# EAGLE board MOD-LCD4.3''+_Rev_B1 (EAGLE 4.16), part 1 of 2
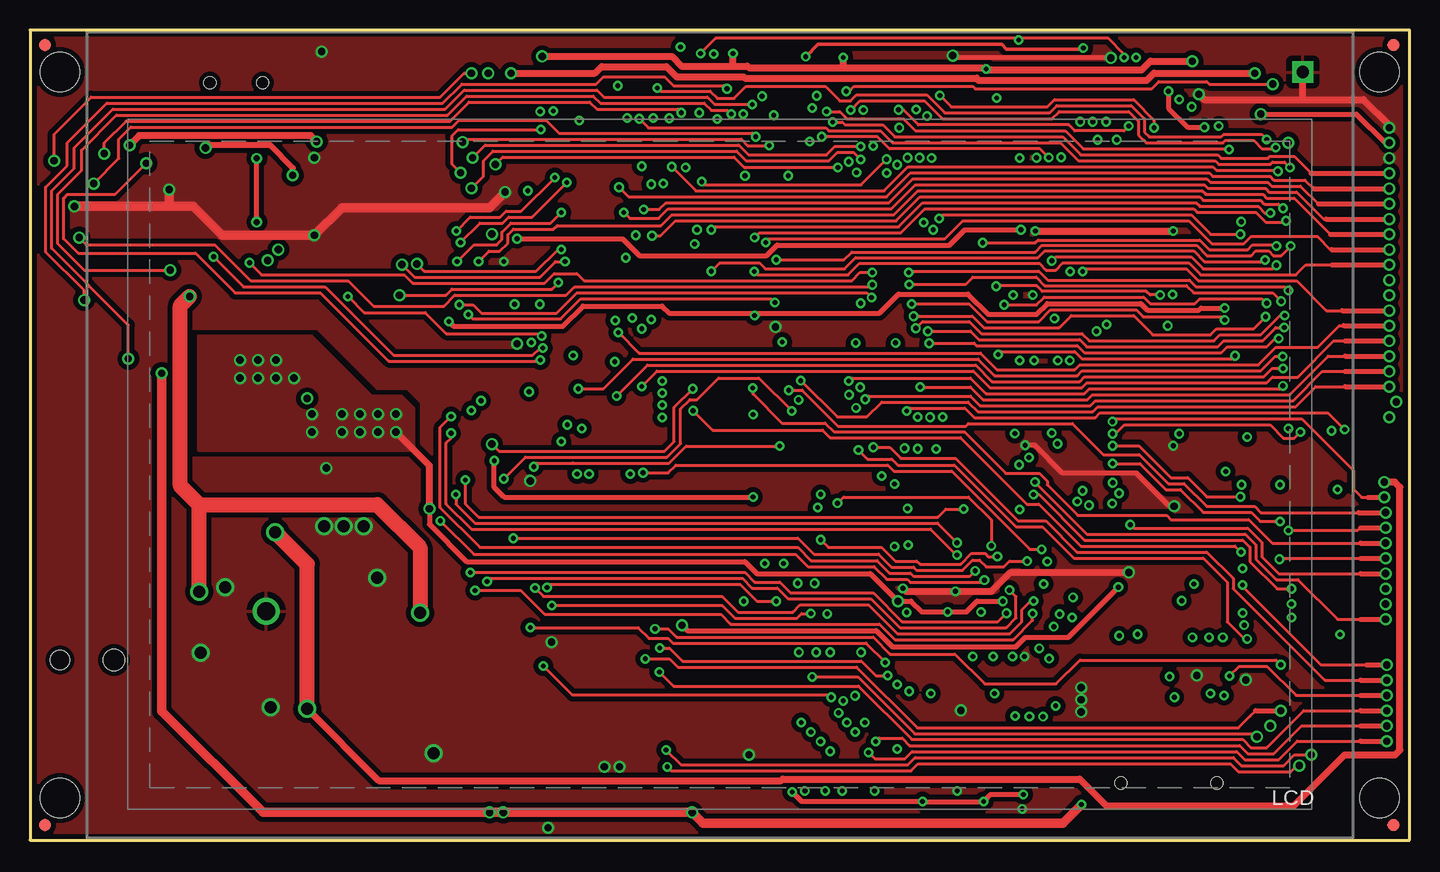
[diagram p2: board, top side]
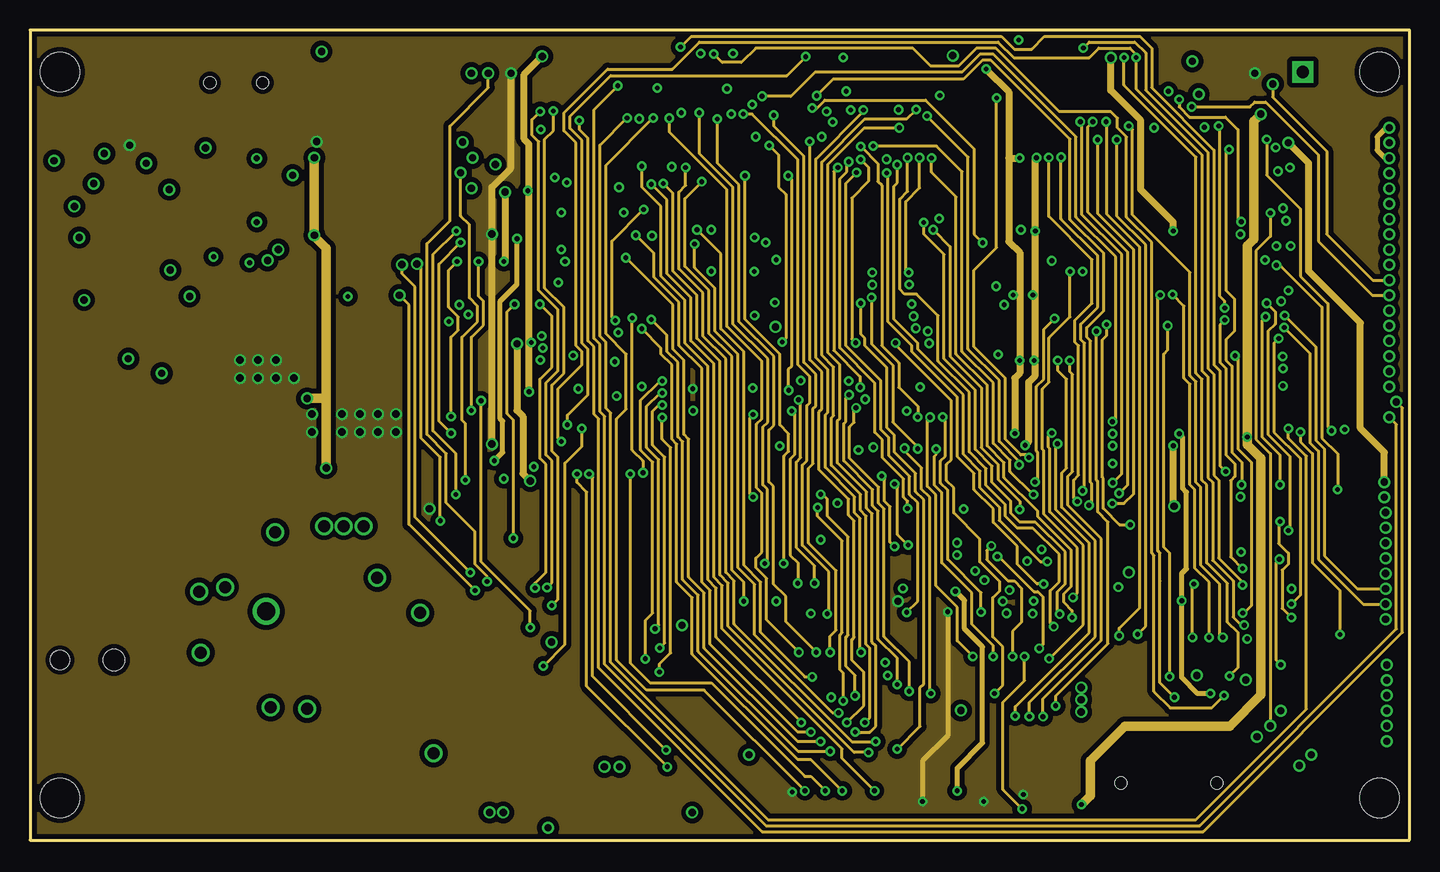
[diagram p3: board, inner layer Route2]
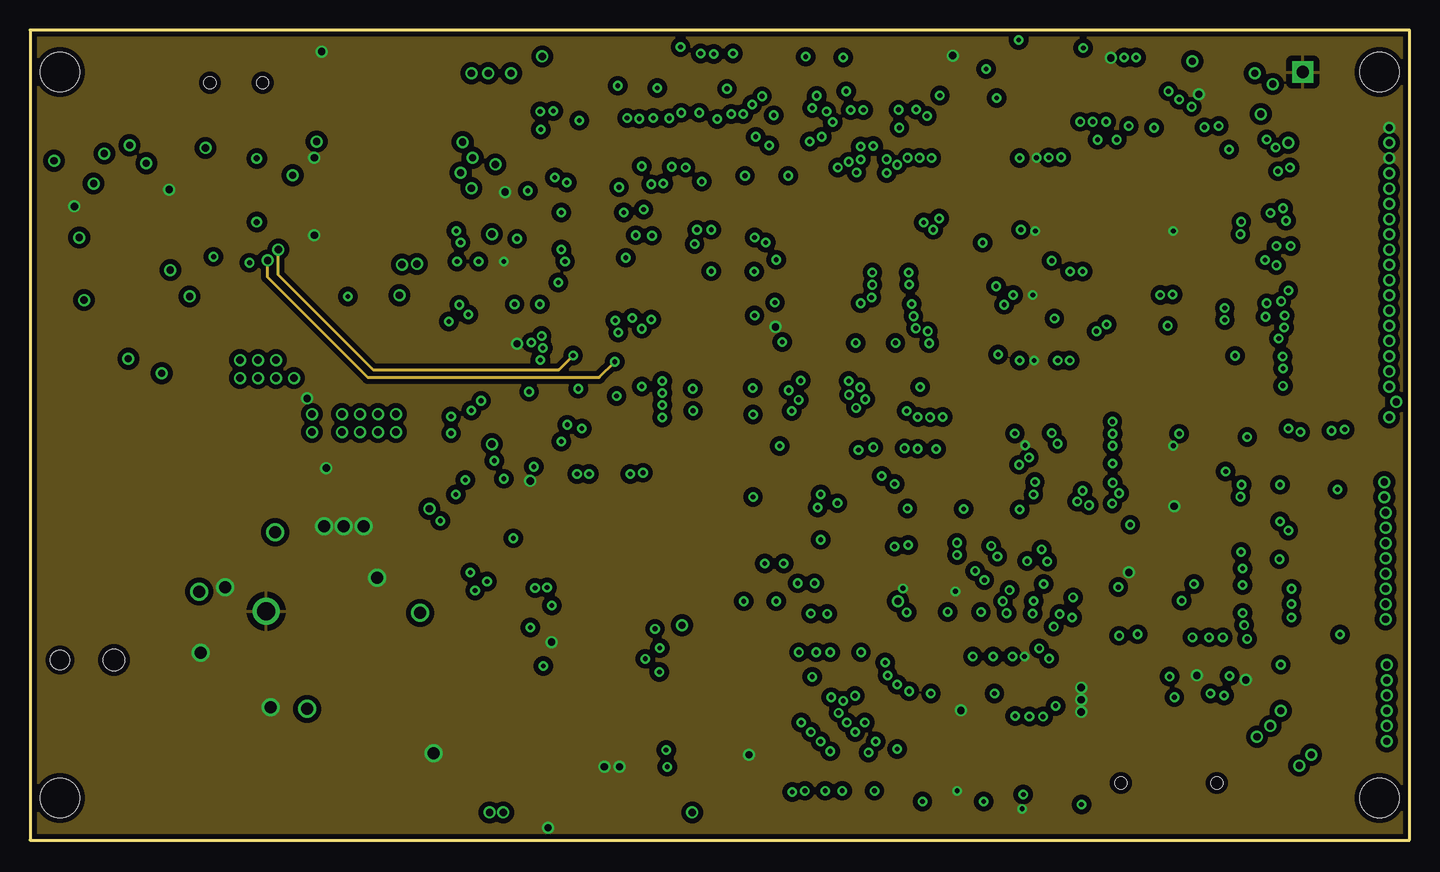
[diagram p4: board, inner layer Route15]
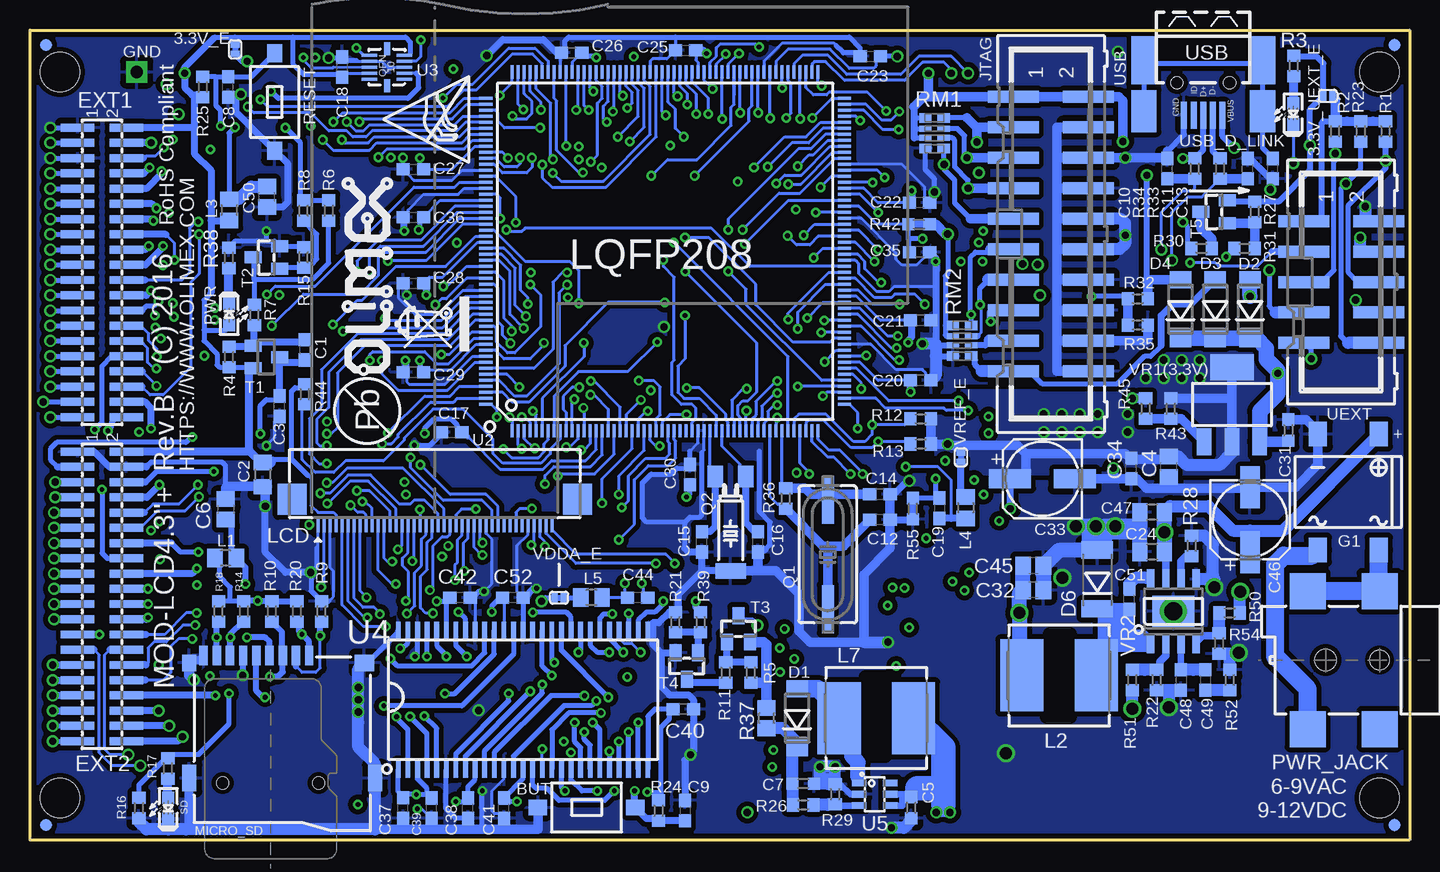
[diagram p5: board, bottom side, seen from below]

Size 115 x 67.5 mm. Coordinates in mm from the lower left corner, seen from the top.
Outline: 0,0 115,0 115,67.5 0,67.5 0,0
Copper layers (1*2*15*16): Top 0.035mm / dielectric 0.5mm / Route2 0.035mm / dielectric 0.5mm / Route15 0.035mm / dielectric 0.5mm / Bottom 0.035mm
Design rules "default": minimum track width 0.2mm, minimum drill 0.4mm, track to track 0.2mm, track to pad 0.2mm, pad to pad 0.2mm, via to via 0.2mm, smd to smd 0mil, copper to edge 0.25mm, drill to drill 0.2mm, minimum pad ring 0.25mm, minimum via ring 0.2mm, stop-mask expansion 2mil, vias tented up to drill 25mil, thermal gap 20mil
Net classes: 1 pwr: width 0.25 mm; 2 gnd: width 0.25 mm, clearance 0.4 mm
Holes 3.3 mm at 2.5,64 2.5,3.5 112.5,3.5 112.5,64
bRestrict: 9 lines

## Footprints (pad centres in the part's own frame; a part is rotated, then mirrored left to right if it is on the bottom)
SJ_1_SMALLER_CLOSE = smd 0.508 x 0.762: 1 -0.381,0; 2 0.381,0
SJ_1_SMALLER = smd 0.508 x 0.762: 1 -0.381,0; 2 0.381,0
SW-TAKT_6X3.5_SMD = smd 1.27 x 1.524: P$1 0,4.064; P$2 0,-4.064
C0603 = smd 1.1 x 1: 1 -0.85,0; 2 0.85,0
C0805_5MIL_DWS = smd 1.27 x 1.524: 1 -1.016,0; 2 1.016,0
C0805 = smd 1.3 x 1.5: 1 -0.85,0; 2 0.85,0
C0603_DWS = smd 1.016 x 1.016: 1 -0.889,0; 2 0.889,0
153CLV-0605 = smd 3.5 x 1.6: + -2.7,0; - 2.7,0
MLL-41 = smd 1.45 x 1.8: A 2.445,0; K -2.445,0
MELF-MLL41 = smd 1.45 x 2.6: 1 -2.445,0; 2 2.445,0
ML40_50MILS_M = smd 0.66 x 2.794: 1 -12.065,-2.032; 2 -12.065,2.032; 3 -10.795,-2.032; 4 -10.795,2.032; 5 -9.525,-2.032; 6 -9.525,2.032; 7 -8.255,-2.032; 8 -8.255,2.032; 9 -6.985,-2.032; 10 -6.985,2.032; 11 -5.715,-2.032; 12 -5.715,2.032; 13 -4.445,-2.032; 14 -4.445,2.032; 15 -3.175,-2.032; 16 -3.175,2.032; 17 -1.905,-2.032; 18 -1.905,2.032; 19 -0.635,-2.032; 20 -0.635,2.032; 21 0.635,-2.032; 22 0.635,2.032; 23 1.905,-2.032; 24 1.905,2.032; 25 3.175,-2.032; 26 3.175,2.032; 27 4.445,-2.032; 28 4.445,2.032; 29 5.715,-2.032; 30 5.715,2.032; 31 6.985,-2.032; 32 6.985,2.032; 33 8.255,-2.032; 34 8.255,2.032; 35 9.525,-2.032; 36 9.525,2.032; 37 10.795,-2.032; 38 10.795,2.032; 39 12.065,-2.032; 40 12.065,2.032
DB104_SMD = smd 1.524 x 2.032: + -2.54,-4.826; - 2.54,-4.826; AC1 2.54,4.826; AC2 -2.54,4.826
TEST_PAD40/70/SQUARE = drill 1.016 pad 1.778 square: P$1 0,0
ML20_S = smd 1 x 4.25: 1 -11.43,-3.125; 2 -11.43,3.125; 3 -8.89,-3.125; 4 -8.89,3.125; 5 -6.35,-3.125; 6 -6.35,3.125; 7 -3.81,-3.125; 8 -3.81,3.125; 9 -1.27,-3.125; 10 -1.27,3.125; 11 1.27,-3.125; 12 1.27,3.125; 13 3.81,-3.125; 14 3.81,3.125; 15 6.35,-3.125; 16 6.35,3.125; 17 8.89,-3.125; 18 8.89,3.125; 19 11.43,-3.125; 20 11.43,3.125
L0805 = smd 1.27 x 1.524: 1 -0.889,0; 2 0.889,0
8X8MM_3131 = smd 3.6 x 6: 1 -3.1,0; 2 3.1,0
GFT043(40PINS) = smd 0.25 x 1.3 bottom: 1 -33.5,7.45; 2 -33,7.45; 3 -32.5,7.45; 4 -32,7.45; 5 -31.5,7.45; 6 -31,7.45; 7 -30.5,7.45; 8 -30,7.45; 9 -29.5,7.45; 10 -29,7.45; 11 -28.5,7.45; 12 -28,7.45; 13 -27.5,7.45; 14 -27,7.45; 15 -26.5,7.45; 16 -26,7.45; 17 -25.5,7.45; 18 -25,7.45; 19 -24.5,7.45; 20 -24,7.45; 21 -23.5,7.45; 22 -23,7.45; 23 -22.5,7.45; 24 -22,7.45; 25 -21.5,7.45; 26 -21,7.45; 27 -20.5,7.45; 28 -20,7.45; 29 -19.5,7.45; 30 -19,7.45; 31 -18.5,7.45; 32 -18,7.45; 33 -17.5,7.45; 34 -17,7.45; 35 -16.5,7.45; 36 -16,7.45; 37 -15.5,7.45; 38 -15,7.45; 39 -14.5,7.45; 40 -14,7.45 | smd 2.4 x 2.6 bottom: P1 -11.85,5.35; P2 -35.65,5.35
TFC-WPAPR-08 = smd 1.6 x 0.7: 1 -7.375,2.25; 2 -7.375,1.15; 3 -7.375,0.05; 4 -7.375,-1.05; 5 -7.375,-2.15; 6 -7.375,-3.25; 7 -7.375,-4.35; 8 -7.375,-5.45; 9 -7.375,-6.55 | smd 1.4 x 1.2: 10 -6.75,-7.75 | smd 1.4 x 1.6: 11 -6.75,6.85 | smd 2.2 x 1.2: 12 2.85,-7.75; 13 2.85,7.75 | hole 1: 3.25,-4.95; 3.25,3.05
LED-0603 = smd 1.016 x 1.016: A 0.889,0; C -0.889,0
PWR-JACK-SMD = smd 3 x 3: 1 6,5.75; 2 0,-5.75; 3 6,-5.75; 4 0,5.75 | hole 1.6: 0,0 | hole 1.8: 4.5,0
HC49/SMD2_THIN&SHORT = smd 4 x 1: 1 -4.564,0; 2 4.564,0
TC26H_3_REPAIR_SMD = smd 1.27 x 1.778: 1 -1.27,0; 2 1.27,0 | smd 2.54 x 1.27: GND 0,7.874
R0603 = smd 1 x 1.1: 1 -0.85,0; 2 0.85,0
R0805 = smd 1.3 x 1.5: 1 -0.85,0; 2 0.85,0
0603_0R = smd 1.016 x 1.016: 1 -0.889,0; 2 0.889,0
R_MATRIX_4 = smd 0.762 x 1.016: 1.1 -1.27,-0.762; 1.2 -1.27,0.762; 4.1 1.27,-0.762; 4.2 1.27,0.762 | smd 0.508 x 1.016: 2.1 -0.381,-0.762; 2.2 -0.381,0.762; 3.1 0.381,-0.762; 3.2 0.381,0.762
SOT23 = smd 1.4 x 1: 1 1.1,-0.95; 2 1.1,0.95; 3 -1.1,0
LQFP208 = smd 0.254 x 1.1: 1 -12.75,-14.95; 2 -12.25,-14.95; 3 -11.75,-14.95; 4 -11.25,-14.95; 5 -10.75,-14.95; 6 -10.25,-14.95; 7 -9.75,-14.95; 8 -9.25,-14.95; 9 -8.75,-14.95; 10 -8.25,-14.95; 11 -7.75,-14.95; 12 -7.25,-14.95; 13 -6.75,-14.95; 14 -6.25,-14.95; 15 -5.75,-14.95; 16 -5.25,-14.95; 17 -4.75,-14.95; 18 -4.25,-14.95; 19 -3.75,-14.95; 20 -3.25,-14.95; 21 -2.75,-14.95; 22 -2.25,-14.95; 23 -1.75,-14.95; 24 -1.25,-14.95; 25 -0.75,-14.95; 26 -0.25,-14.95; 27 0.25,-14.95; 28 0.75,-14.95; 29 1.25,-14.95; 30 1.75,-14.95; 31 2.25,-14.95; 32 2.75,-14.95; 33 3.25,-14.95; 34 3.75,-14.95; 35 4.25,-14.95; 36 4.75,-14.95; 37 5.25,-14.95; 38 5.75,-14.95; 39 6.25,-14.95; 40 6.75,-14.95; 41 7.25,-14.95; 42 7.75,-14.95; 43 8.25,-14.95; 44 8.75,-14.95; 45 9.25,-14.95; 46 9.75,-14.95; 47 10.25,-14.95; 48 10.75,-14.95; 49 11.25,-14.95; 50 11.75,-14.95; 51 12.25,-14.95; 52 12.75,-14.95; 105 12.75,14.95; 106 12.25,14.95; 107 11.75,14.95; 108 11.25,14.95; 109 10.75,14.95; 110 10.25,14.95; 111 9.75,14.95; 112 9.25,14.95; 113 8.75,14.95; 114 8.25,14.95; 115 7.75,14.95; 116 7.25,14.95; 117 6.75,14.95; 118 6.25,14.95; 119 5.75,14.95; 120 5.25,14.95; 121 4.75,14.95; 122 4.25,14.95; 123 3.75,14.95; 124 3.25,14.95; 125 2.75,14.95; 126 2.25,14.95; 127 1.75,14.95; 128 1.25,14.95; 129 0.75,14.95; 130 0.25,14.95; 131 -0.25,14.95; 132 -0.75,14.95; 133 -1.25,14.95; 134 -1.75,14.95; 135 -2.25,14.95; 136 -2.75,14.95; 137 -3.25,14.95; 138 -3.75,14.95; 139 -4.25,14.95; 140 -4.75,14.95; 141 -5.25,14.95; 142 -5.75,14.95; 143 -6.25,14.95; 144 -6.75,14.95; 145 -7.25,14.95; 146 -7.75,14.95; 147 -8.25,14.95; 148 -8.75,14.95; 149 -9.25,14.95; 150 -9.75,14.95; 151 -10.25,14.95; 152 -10.75,14.95; 153 -11.25,14.95; 154 -11.75,14.95; 155 -12.25,14.95; 156 -12.75,14.95 | smd 1.1 x 0.254: 53 14.95,-12.75; 54 14.95,-12.25; 55 14.95,-11.75; 56 14.95,-11.25; 57 14.95,-10.75; 58 14.95,-10.25; 59 14.95,-9.75; 60 14.95,-9.25; 61 14.95,-8.75; 62 14.95,-8.25; 63 14.95,-7.75; 64 14.95,-7.25; 65 14.95,-6.75; 66 14.95,-6.25; 67 14.95,-5.75; 68 14.95,-5.25; 69 14.95,-4.75; 70 14.95,-4.25; 71 14.95,-3.75; 72 14.95,-3.25; 73 14.95,-2.75; 74 14.95,-2.25; 75 14.95,-1.75; 76 14.95,-1.25; 77 14.95,-0.75; 78 14.95,-0.25; 79 14.95,0.25; 80 14.95,0.75; 81 14.95,1.25; 82 14.95,1.75; 83 14.95,2.25; 84 14.95,2.75; 85 14.95,3.25; 86 14.95,3.75; 87 14.95,4.25; 88 14.95,4.75; 89 14.95,5.25; 90 14.95,5.75; 91 14.95,6.25; 92 14.95,6.75; 93 14.95,7.25; 94 14.95,7.75; 95 14.95,8.25; 96 14.95,8.75; 97 14.95,9.25; 98 14.95,9.75; 99 14.95,10.25; 100 14.95,10.75; 101 14.95,11.25; 102 14.95,11.75; 103 14.95,12.25; 104 14.95,12.75; 157 -14.95,12.75; 158 -14.95,12.25; 159 -14.95,11.75; 160 -14.95,11.25; 161 -14.95,10.75; 162 -14.95,10.25; 163 -14.95,9.75; 164 -14.95,9.25; 165 -14.95,8.75; 166 -14.95,8.25; 167 -14.95,7.75; 168 -14.95,7.25; 169 -14.95,6.75; 170 -14.95,6.25; 171 -14.95,5.75; 172 -14.95,5.25; 173 -14.95,4.75; 174 -14.95,4.25; 175 -14.95,3.75; 176 -14.95,3.25; 177 -14.95,2.75; 178 -14.95,2.25; 179 -14.95,1.75; 180 -14.95,1.25; 181 -14.95,0.75; 182 -14.95,0.25; 183 -14.95,-0.25; 184 -14.95,-0.75; 185 -14.95,-1.25; 186 -14.95,-1.75; 187 -14.95,-2.25; 188 -14.95,-2.75; 189 -14.95,-3.25; 190 -14.95,-3.75; 191 -14.95,-4.25; 192 -14.95,-4.75; 193 -14.95,-5.25; 194 -14.95,-5.75; 195 -14.95,-6.25; 196 -14.95,-6.75; 197 -14.95,-7.25; 198 -14.95,-7.75; 199 -14.95,-8.25; 200 -14.95,-8.75; 201 -14.95,-9.25; 202 -14.95,-9.75; 203 -14.95,-10.25; 204 -14.95,-10.75; 205 -14.95,-11.25; 206 -14.95,-11.75; 207 -14.95,-12.25; 208 -14.95,-12.75
QFN10 = smd 0.25 x 1.3: 1 -1,-1.45; 2 -0.5,-1.45; 3 0,-1.45; 4 0.5,-1.45; 5 1,-1.45; 6 1,1.45; 7 0.5,1.45; 8 0,1.45; 9 -0.5,1.45; 10 -1,1.45 | smd 1.1 x 0.5: NC1 -1.55,0; NC2 1.55,0
54TSOPII = smd 0.4 x 1.4: 1 -10.4,-6; 2 -9.6,-6; 3 -8.8,-6; 4 -8,-6; 5 -7.2,-6; 6 -6.4,-6; 7 -5.6,-6; 8 -4.8,-6; 9 -4,-6; 10 -3.2,-6; 11 -2.4,-6; 12 -1.6,-6; 13 -0.8,-6; 14 0,-6; 15 0.8,-6; 16 1.6,-6; 17 2.4,-6; 18 3.2,-6; 19 4,-6; 20 4.8,-6; 21 5.6,-6; 22 6.4,-6; 23 7.2,-6; 24 8,-6; 25 8.8,-6; 26 9.6,-6; 27 10.4,-6; 28 10.4,5.6; 29 9.6,5.6; 30 8.8,5.6; 31 8,5.6; 32 7.2,5.6; 33 6.4,5.6; 34 5.6,5.6; 35 4.8,5.6; 36 4,5.6; 37 3.2,5.6; 38 2.4,5.6; 39 1.6,5.6; 40 0.8,5.6; 41 0,5.6; 42 -0.8,5.6; 43 -1.6,5.6; 44 -2.4,5.6; 45 -3.2,5.6; 46 -4,5.6; 47 -4.8,5.6; 48 -5.6,5.6; 49 -6.4,5.6; 50 -7.2,5.6; 51 -8,5.6; 52 -8.8,5.6; 53 -9.6,5.6; 54 -10.4,5.6
SOT23-6 = smd 1.2 x 0.55: 1 1.3,-0.95; 2 1.3,0; 3 1.3,0.95; 4 -1.3,0.95; 5 -1.3,0; 6 -1.3,-0.95
FIDUCIAL-1X2 = smd 1 x 1: 1 0,0
ML10_S = smd 1 x 4.25: 1 -5.08,-3.125; 2 -5.08,3.125; 3 -2.54,-3.125; 4 -2.54,3.125; 5 0,-3.125; 6 0,3.125; 7 2.54,-3.125; 8 2.54,3.125; 9 5.08,-3.125; 10 5.08,3.125
USB_MINI_9PIN = smd 2.25 x 0.5: D+ -5.246,0; D- -5.246,-0.8; GND -5.246,1.6; ID -5.246,0.8; VBUS -5.246,-1.6 | smd 4 x 2.1: GND1 -0.64,-4.95; GND3 -0.64,4.95 | smd 3.5 x 2.1: GND2 -4.89,-4.95; GND4 -4.89,4.95 | hole 1: -2.54,-2.2; -2.54,2.2
SOT223 = smd 1.219 x 2.235: 1 -2.311,-3.099; 2 0,-3.099; 3 2.311,-3.099 | smd 3.6 x 2.2: 4 0,3.099
SOIC8E = smd 0.61 x 1.6: 1 -1.905,-2.7; 2 -0.635,-2.7; 3 0.635,-2.7; 4 1.905,-2.7; 5 1.905,2.7; 6 0.635,2.7; 7 -0.635,2.7; 8 -1.905,2.7 | smd 3.51 x 2.62: EP 0,0 | drill 1.5 round: EP1 0,0

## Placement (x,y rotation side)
3.3V_E  close  [SJ_1_SMALLER_CLOSE]  97.9,65.9 270 bottom
3.3V_UEXT_E  open  [SJ_1_SMALLER]  6.8,62 180 bottom
BUT  T1107A/6x3.8x2.5  [SW-TAKT_6X3.5_SMD]  68.6,2.7 270 bottom
C1  (NA)100n  [C0603]  92.1,40.85 270 bottom
C2  10uF/16V  [C0805_5MIL_DWS]  95.6,30.45 270 bottom
C3  100n  [C0603]  94.2,36.15 90 bottom
C4  47uF/6.3V  [C0805]  20.07,31.11 90 bottom
C5  22uF/6.3V  [C0603_DWS]  41.54,2.69 270 bottom
C6  47uF/6.3V  [C0805]  98.68,27.56 270 bottom
C7  2.2uF/50V  [C0603_DWS]  50.55,4.7 0 bottom
C8  100n  [C0603]  98.5,62.75 90 bottom
C9  (NA)100n  [C0603]  60.4,2.45 270 bottom
C10  18p(NA)  [C0603]  20.2,55.95 90 bottom
C11  18p(NA)  [C0603]  13.5,55.95 90 bottom
C12  22p  [C0603]  44.15,26.7 180 bottom
C13  10n  [C0603]  11.4,55.95 90 bottom
C14  22p  [C0603]  44.15,28.8 180 bottom
C15  10p  [C0603]  59,24.85 90 bottom
C16  10p  [C0603]  54.3,24.85 90 bottom
C17  100n  [C0603]  79.85,34 0 bottom
C18  NA(2.2uF/6.3V)  [C0603]  89,64.4 270 bottom
C19  100n  [C0603]  39.2,27.65 270 bottom
C20  100n  [C0603]  40.75,38.3 180 bottom
C21  100n  [C0603]  40.75,43.3 180 bottom
C22  100n  [C0603]  40.85,53.1 180 bottom
C23  100n  [C0603]  44.95,65.3 0 bottom
C24  10uF/16V  [C0805_5MIL_DWS]  21.46,24 180 bottom
C25  100n  [C0603]  60.35,65.8 0 bottom
C26  100n  [C0603]  69.85,65.6 0 bottom
C27  100n  [C0603]  83.05,55.9 0 bottom
C28  100n  [C0603]  83.05,46.4 0 bottom
C29  100n  [C0603]  83.05,39 0 bottom
C30  100n  [C0603]  60,30.45 270 bottom
C31  2.2uF/6.3V  [C0603_DWS]  10.1,34.15 90 bottom
C32  47uF/6.3V  [C0805]  31.37,20.83 180 bottom
C33  220uF/16V/SMD  [153CLV-0605]  30.6,30.1 0 bottom
C34  100n  [C0603]  23.2,30.95 90 bottom
C35  100n  [C0603]  40.85,49 180 bottom
C36  100n  [C0603]  83.05,51.9 0 bottom
C37  100n  [C0603]  83.9,2.67 90 bottom
C38  100n  [C0603]  78.5,2.65 90 bottom
C39  100n  [C0603]  81.5,2.66 90 bottom
C40  100n  [C0603]  60.55,10.9 180 bottom
C41  100n  [C0603]  75.5,2.65 90 bottom
C42  100n  [C0603]  79.15,20.2 180 bottom
C44  100n  [C0603]  64.35,20.2 180 bottom
C45  NA(47uF/6.3V)  [C0805]  31.37,22.86 180 bottom
C46  220uF/16V/SMD  [153CLV-0605]  13.3,26.7 90 bottom
C47  10uF/16V  [C0805_5MIL_DWS]  21.46,27.3 180 bottom
C48  NA  [C0603]  19.05,13.34 270 bottom
C49  150pF  [C0603]  17.02,13.34 270 bottom
C50  47uF/6.3V  [C0805]  95.25,53.59 90 bottom
C51  100n  [C0603]  23.37,20.07 90 bottom
C52  100n  [C0603]  74.75,20.2 180 bottom
D1  1N5819S  [MLL-41]  51.05,10.16 90 bottom
D2  1N5819S  [MLL-41]  13.3,44.24 90 bottom
D3  1N5819S  [MLL-41]  16.2,44.24 90 bottom
D4  1N5819S  [MLL-41]  19.1,44.24 90 bottom
D6  SS34  [MELF-MLL41]  26.04,21.72 90 bottom
EXT1  (NA)GPH127-02x20  [ML40_50MILS_M]  109,47.3 270 bottom
EXT2  (NA)GPH127-02x20  [ML40_50MILS_M]  109,20.3 270 bottom
G1  DB104(SMD)  [DB104_SMD]  5.1,29 180 bottom
GND  TESTPAD3  [TEST_PAD40/70/SQUARE]  106.1,64 0 bottom
JTAG  GBH-254SMT-40  [ML20_S]  29.9,50.5 270 bottom
L1  470nH  [L0805]  98.69,23.5 180 bottom
L2  15uH/YS75  [8X8MM_3131]  29.21,13.72 180 bottom
L3  NA(470nH)  [L0805]  98.4,52.51 270 bottom
L4  470nH  [L0805]  37,27.69 270 bottom
L5  470nH  [L0805]  68.2,20.2 180 bottom
L7  22uH/YS75  [8X8MM_3131]  44.45,10.16 180 bottom
LCD  GFT043+(FPV-WZA21-40-LF)  [GFT043(40PINS)]  57.5,33.75 180 top
MICRO_SD  TFC-WPAPR-08  [TFC-WPAPR-08]  93.98,8 270 bottom
PWR  0603_RED  [LED-0603]  98.4,43.79 270 bottom
PWR_JACK  PWR-JACK-SMD  [PWR-JACK-SMD]  2.5,15 180 bottom
Q1  12MHz/30ppm/20pF/HC49/SMD  [HC49/SMD2_THIN&SHORT]  48.5,23.8 90 bottom
Q2  32768/6pF  [TC26H_3_REPAIR_SMD]  56.6,30.3 180 bottom
R1  4.7K  [R0603]  2,59.05 90 bottom
R2  4.7K  [R0603]  6.2,59.05 90 bottom
R3  549R/1%  [R0603]  9.65,64.52 90 bottom
R4  20K/1%  [R0603]  98.4,40.25 90 bottom
R5  33K  [R0603]  54.9,13.95 90 bottom
R6  NA  [R0603]  90.1,52.45 90 bottom
R7  1K  [R0603]  96.3,43.75 90 bottom
R8  33K  [R0603]  92.2,52.45 90 bottom
R9  1M  [R0603]  90.7,19.05 270 bottom
R10  10K  [R0603]  94.84,19.05 270 bottom
R11  10K  [R0603]  57,13.95 90 bottom
R12  4.7K  [R0603]  40.75,35.1 180 bottom
R13  4.7K  [R0603]  40.75,33 180 bottom
R14  33K  [R0603]  97.18,19.05 270 bottom
R15  NA  [R0603]  92.2,48.55 270 bottom
R16  2.2K  [R0603]  105.92,2.67 90 bottom
R17  1K  [R0603]  103.5,5.97 270 bottom
R18  33K  [R0603]  99.27,19.05 270 bottom
R20  33K  [R0603]  92.75,19.05 270 bottom
R21  33K  [R0603]  61.2,18.15 90 bottom
R22  33K  [R0603]  21.08,13.34 90 bottom
R23  33K  [R0603]  4.06,59.05 90 bottom
R24  33K  [R0603]  62.6,2.45 90 bottom
R25  33K  [R0603]  100.6,62.75 270 bottom
R26  24k/1%  [R0603]  50.55,2.92 180 bottom
R27  10K  [R0603]  12.9,52.35 270 bottom
R28  100K  [R0603]  18.16,24.51 270 bottom
R29  549R/1%  [R0603]  47.88,3.81 270 bottom
R30  1.5K/1%  [R0603]  17.35,49.3 0 bottom
R31  2.2K  [R0603]  13.75,49.3 0 bottom
R32  10K  [R0603]  22.65,45.1 180 bottom
R33  33  [R0603]  15.8,55.95 270 bottom
R34  33  [R0603]  17.9,55.95 270 bottom
R35  20K/1%  [R0603]  22.65,42.9 0 bottom
R36  NA  [R0603]  52,28.45 270 bottom
R37  200R  [R0805]  53.59,10.16 90 bottom
R38  1K  [R0603]  98.42,48.51 90 bottom
R39  4.7K  [R0603]  59.1,18.15 270 bottom
R42  [0603_0R]  40.89,51.3 0 bottom
R43  240R/1%  [R0603]  19.9,35.95 90 bottom
R44  10K  [R0603]  92.1,37.15 90 bottom
R45  390R/1%  [R0603]  22,35.95 270 bottom
R50  10K/1%  [R0603]  14.99,18.92 0 bottom
R51  100K  [R0603]  23.11,13.34 270 bottom
R52  100K  [R0603]  14.99,13.34 270 bottom
R54  1.82K/1%  [R0603]  15.88,16.38 90 bottom
R55  [0603_0R]  41.4,27.61 270 bottom
RESET  T1107A/6x3.8x2.5  [SW-TAKT_6X3.5_SMD]  94.6,61.5 0 bottom
RM1  10K  [R_MATRIX_4]  39.6,58.9 270 bottom
RM2  10K  [R_MATRIX_4]  37.3,41.6 270 bottom
SD  0603_GREEN  [LED-0603]  103.48,2.64 90 bottom
T1  IRLM6402  [SOT23]  95.3,40.25 180 bottom
T2  BC817  [SOT23]  95.3,48.55 0 bottom
T3  BC807  [SOT23]  55.95,17.6 270 bottom
T4  BC817  [SOT23]  60.25,14.5 90 bottom
T5  BC807  [SOT23]  16.3,52.35 0 bottom
U2  LPC1788FBD208.551  [LQFP208]  62.05,49.05 0 bottom
U3  NA(SMB380,(QFN10))  [QFN10]  85.25,64.4 90 bottom
U4  K4S561632C-TC/L75  [54TSOPII]  73.9,11.9 0 bottom
U5  MT3608  [SOT23-6]  44.58,3.81 180 bottom
U$1  FIDUCIAL1X2  [FIDUCIAL-1X2]  1.25,1.25 0 top
U$2  FIDUCIAL1X2  [FIDUCIAL-1X2]  1.25,66.25 0 top
U$3  FIDUCIAL1X2  [FIDUCIAL-1X2]  113.65,1.25 0 top
U$4  [PB]  86.9,35.75 90 bottom
U$5  [ESD_SYMBOL]  78.4,56.5 90 bottom
U$6  FIDUCIAL1X2  [FIDUCIAL-1X2]  113.65,1.25 0 bottom
U$7  [OLIMEX1_V]  84.6,56.4 90 bottom
U$8  [RECYCLE_BIN1/8]  78.41,40.72 90 bottom
U$9  FIDUCIAL1X2  [FIDUCIAL-1X2]  113.65,66.25 0 top
U$10  FIDUCIAL1X2  [FIDUCIAL-1X2]  1.25,1.25 0 bottom
U$11  [ROHS_T_STOP]  17.2,17.31 0 top
U$12  FIDUCIAL1X2  [FIDUCIAL-1X2]  1.25,66.25 0 bottom
U$13  FIDUCIAL1X2  [FIDUCIAL-1X2]  113.65,66.25 0 bottom
UEXT  GBH254SMT-10  [ML10_S]  5.7,46.5 270 bottom
USB  USB_MINI  [USB_MINI_9PIN]  17.2,65.64 90 bottom
USB_D_LINK  0603_YELLOW  [LED-0603]  9.7,60.51 90 bottom
VDDA_E  close  [SJ_1_SMALLER_CLOSE]  70.9,20.2 0 bottom
VR1(3.3V)  LM1117IMPX-ADJ  [SOT223]  14.8,36.3 0 bottom
VR2  MP1584EN(SOIC8E)  [SOIC8E]  19.68,19.05 0 bottom
VREF_E  close  [SJ_1_SMALLER_CLOSE]  37.4,31.9 270 bottom

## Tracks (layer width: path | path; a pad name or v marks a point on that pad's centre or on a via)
3.3V_A  (via drill 0.4)
  Route2 0.25: v65.4,21.4 65.4,22.84 63.88,24.36 63.88,31.5 64.25,31.86 64.25,36.51 v64.07,36.68
  Bottom 0.25: C44.2 65.4,20.2 | 65.4,20.2 v65.4,21.4 | 65.4,20.2 L5.1 | v64.07,36.68 65.3,35.45 U2.20
3.3V_MCU  (via drill 0.4, 0.6)
  Top 0.6: v42.7,65.3 53.5,65.3 54.3,64.5 58.6,64.5 | 58.6,64.5 v58.6,65.55 | 58.6,64.5 59.8,64.5 59.92,64.38 67.8,64.38 | 67.8,64.38 v67.8,65.2 | 67.8,64.38 79.6,64.38 79.7,64.28 | 79.7,64.28 v79.7,64.25 | 79.7,64.28 79.8,64.17 92.67,64.17 93.4,64.9 v96.9,64.9
  Route2 0.6: 41.6,54.1 41.6,58 41.2,58.4 41.2,63.8 v42.7,65.3 | 41.6,41.45 41.6,54.1 | 41.6,54.1 v41.5,54.1 | v41.6,37.35 41.6,41.45 | 41.6,41.45 v41.8,41.45 | 81.6,56.83 81.6,49.88 82.5,48.98 82.5,45.42 | 82.5,45.42 v82.5,39.95 82.5,38.9 82.1,38.5 v82.1,33.88 | v79.7,64.25 81.6,62.35 81.6,56.83 | 81.6,56.83 v82.5,56.83 | 82.5,45.42 v81.95,45.42
  Bottom 0.25: C23.2 44.5,64.9 44.5,64.5 44.7,64.3 46.7,64.3 48.3,65.9 51.8,65.9 52.8,64.9 U2.112 | C25.2 59.5,65 59.3,64.8 U2.125 | U2.165 77.9,57.8 79.8,55.9 C27.2 82.5,56.2 v82.5,56.83 | U2.181 77.7,49.8 80.6,46.9 81.7,46.9 C28.2 | C29.2 82,39.2 79.9,39.2 77.8,41.3 U2.198 | U2.89 45.5,54.3 44.3,53.1 C22.2 41.5,53.3 | U2.71 46.1,45.3 44.1,43.3 C21.2 41.5,43.2 | 45.8,39.8 44.3,38.3 C20.2 | 78.5,33.6 75.8,30.9 72.22,30.9 71.5,31.62 68.71,31.62 67.8,32.53 U2.15 | U2.146 69.8,64.82 69.02,65.6 C26.2
  Bottom 0.254: 45.8,39.8 U2.60
  Bottom 0.4: v42.7,65.3 C23.2 | v67.8,65.2 67.9,65.3 68.7,65.3 C26.2 | C29.2 82.5,39.3 v82.5,39.95
  Bottom 0.406: v82.1,33.88 82.1,34.3 81.3,35.1 79.9,35.1 79.4,34.6 79.4,34.4 C17.2 78.9,34 78.5,33.6
  Bottom 0.6: v58.6,65.55 58.85,65.8 C25.2 | v41.5,54.1 41.5,53.3 | v41.8,41.45 41.8,41.62 41.5,41.92 41.5,43.2 | v41.6,37.35 C20.2 | v96.9,64.9 97.28,64.9 3.3V_E.2 | v81.95,45.42 81.95,46.15 C28.2
+5V  (via drill 0.4, 0.6)
  Top 0.4: v102.6,60.5 110.57,60.5 112.97,58.09 v113.3,58.09
  Top 0.8: v39.45,2.3 v55.2,2.3 56.1,1.4 86.1,1.4 v87.66,2.96 | v10.98,38.9 10.98,10.73 19.42,2.3 v38.31,2.3 v39.45,2.3 | v39.45,2.3 55.33,2.3
  Route2 0.8: v102.6,60.5 102,59.9 102,50.05 101.47,49.52 v101.47,33.58 101.47,32.92 102.6,31.8 102.6,12.1 100,9.5 91.29,9.5 88.39,6.6 88.39,3.69 v87.66,2.96
  Bottom 0.4: v101.47,33.58 101.56,33.58 101.99,33.15 112.75,33.15 113.3,32.6 113.3,31.7 112.69,31.09 | v113.3,58.09 EXT1.3
  Bottom 0.559: C5.1 41.53,3.56 | C5.1 | 42.29,3.81 41.53,3.81 C5.1 | U5.4 42.29,2.86 42.29,3.81 | 42.29,3.81 U5.5
  Bottom 0.6: 112.69,31.09 EXT2.3 | D3.K 16.3,41.8
  Bottom 0.762: 38.86,2.3 38.86,2.92 | C5.1 41.54,4.32 41.02,4.32
  Bottom 0.8: v38.31,2.3 38.86,2.3 v39.45,2.3
  Bottom 0.889: 10.16,33.26 10.16,33.27 | 10.16,33.26 C31.1 | VR1(3.3V).3 10.16,33.2 10.16,33.26
  Bottom 1.3: VR1(3.3V).3 12.49,35.71 10.98,37.22 v10.98,38.9 10.98,39.11 11.94,40.07 11.94,40.99 12.75,41.8 D2.K D3.K D4.K
  Bottom 2.032: L7.1 38.86,7.67 38.86,4.32 | 38.86,2.92 38.86,4.32 | 38.86,4.32 41.02,4.32
+5V_EXT  (via drill 0.6, 1)
  Top 1.27: 14.1,27.94 12.53,29.5 12.53,44.53 v13.3,45.3 | v14.1,20.7 14.1,27.94 | 14.1,27.94 28.96,27.94 32.51,24.38 v32.51,18.92
  Bottom 1.016: R50.2 14.14,20.66 v14.1,20.7
  Bottom 1.27: v13.3,45.3 D2.A | C45.2 C32.2 32.26,20.83 32.51,20.57 v32.51,18.92 32.51,13.92 L2.2
+5V_JTAG
  Bottom 0.4: JTAG.19 31.67,39.07 30.6,38 24.4,38 22.1,40.3 21.6,40.3 20.7,41.2
  Bottom 0.5: RM2.4.2 36.23,40.02 36.23,39.62 35.67,39.07
  Bottom 0.6: D3.A 18.19,44.7 19.7,44.7 20.7,43.7 20.7,41.2
  Bottom 1: JTAG.19 35.67,39.07
+5V_USB  (via drill 0.6)
  Top 0.5: v21.9,55.4 21.9,56 20,57.9 14.85,57.9 v14.62,57.67
  Bottom 0.5: USB.VBUS 15.6,58.65 v14.62,57.67 | 21.8,46.69 21.9,46.79 v21.9,55.4
  Bottom 0.8: D4.A 21.8,46.69 R32.1
+12V
  Bottom 1.016: 51.05,7.75 D1.K | 51.05,7.75 51.05,8.13 52.24,9.31 R37.1 | 51.05,7.75 51.44,7.37 C7.1 51.44,2.96 R26.2
+24V  (via drill 0.6, 1)
  Top 0.6: v112.9,29.82 113.78,29.82 114.2,29.4 114.2,7.5 113.8,7.1 109.6,7.1 105.34,2.84 89.74,2.84 87.5,5.08 62.74,5.08 62.61,4.95 29.08,4.95 v23.11,10.92
  Top 1.27: v23.11,10.92 23.11,22.99 v20.45,25.65
  Route2 0.6: v112.9,29.82 112.9,32.3 110.9,34.3 110.9,43.1 106.6,47.4 106.6,56.4 v104.91,58.09
  Bottom 0.6: v112.9,29.82 EXT2.5 | v104.91,58.09 EXT1.4 | C46.+ 13.3,23.02
  Bottom 0.635: VR2.7 20.32,23.88 C24.1
  Bottom 0.8: 13.3,25.78 C46.+
  Bottom 1: 13.3,25.78 10.54,25.78 2.56,33.76 G1.+ | 13.3,25.78 13.3,23.02 | 13.3,25.78 14.73,25.78 16.76,27.81
  Bottom 1.016: 16.76,27.81 19.94,27.81 C47.1 | v23.11,10.92 R51.2
  Bottom 1.27: C47.1 v20.45,25.65 C24.1
A0  (via drill 0.4)
  Route2 0.25: v66.7,7.4 64,7.4 55.7,15.7 55.7,20.4 54.4,21.7 54.4,33.2 54,33.6 54,39.8 53.1,40.7 53.1,42.08 v51.8,43.38
  Bottom 0.25: v51.8,43.38 51.8,43.9 48.4,47.3 U2.75
  Bottom 0.4: v66.7,7.4 U4.23
A1  (via drill 0.4)
  Route2 0.25: v65.9,8.2 64,8.2 56.2,16 56.2,20.6 54.9,21.9 54.9,33.4 54.5,33.8 54.5,40 53.6,40.9 53.6,44.6 v49.67,48.52
  Bottom 0.25: v49.67,48.52 48.9,49.3 U2.79
  Bottom 0.4: U4.24 v65.9,8.2
A2  (via drill 0.4)
  Route2 0.25: v65.1,9 64,9 56.7,16.3 56.7,20.8 56,21.5 56,39.3 54.1,41.2 54.1,44.8 52,46.9 52,48.9 v50.5,50.4
  Bottom 0.25: v50.5,50.4 49.6,51.3 U2.83
  Bottom 0.4: U4.25 v65.1,9
A3  (via drill 0.4)
  Route2 0.25: v64.3,9.8 57.2,16.9 57.2,21 56.5,21.7 56.5,39.5 54.6,41.4 54.6,45 52.6,47 52.6,52.8 51,54.4 v51,56.15
  Bottom 0.25: v51,56.15 50.05,57.1 49.7,57.1 48.5,58.3 U2.97
  Bottom 0.4: U4.26 v64.3,9.8
A4  (via drill 0.4)
  Top 0.25: v43.1,21.05 43.35,21.3 59.2,21.3 60.6,19.9 v62.2,19.9
  Route2 0.25: v43.1,21.05 43.5,21.45 43.5,31.6 43,32.1 43,38.1 44,39.1 44,44.2 42.4,45.8 42.4,58.2 41.85,58.75 41.85,60.02 v42.52,60.7
  Bottom 0.25: v42.52,60.7 43.23,60 44,60 45.3,61.3 U2.103
  Bottom 0.4: U4.29 64.3,18.3 63.6,19 62.9,19 62.2,19.7 v62.2,19.9
A5  (via drill 0.4)
  Top 0.25: v65.1,18.88 64.33,18.88 63.95,18.5 58.75,18.5 57.7,19.55 v43.5,19.55 43.48,19.55
  Route2 0.25: v43.5,19.55 44,20.05 44,31.9 43.5,32.4 43.5,37.9 44.5,38.9 44.5,44.4 42.9,46 42.9,58.4 43.62,59.12 v43.62,60.75
  Bottom 0.25: U2.107 50.3,62.7 49.7,62.1 48.6,62.1 48.4,62.3 45.17,62.3 v43.62,60.75
  Bottom 0.4: v65.1,18.88 U4.30
A6  (via drill 0.4)
  Route2 0.25: v64.1,15.65 61.4,18.35 61.4,21.8 60.5,22.7 60.5,23.5 61,24 61,28.92 60.58,29.34 60.58,34.67 61,35.09 61,39.9 58.1,42.8 58.1,54.2 53.3,59 v53.3,60.15
  Bottom 0.25: v64.1,15.65 64.85,16.4 65.5,16.4 65.9,16.8 65.9,16.9 | v53.3,60.15 U2.113
  Bottom 0.4: U4.31 65.9,16.9
A7  (via drill 0.4)
  Route2 0.25: v65.55,15.65 63,18.2 63,20.3 61.98,21.32 61.98,29.46 61.59,29.84 61.59,34.16 62,34.57 62,40.3 59.1,43.2 59.1,54.6 57.3,56.4 v57.3,60.08
  Bottom 0.25: v57.3,60.08 U2.121
  Bottom 0.4: U4.32 66.7,16.8 v65.55,15.65
A8  (via drill 0.4)
  Route2 0.25: v66.45,18.85 66.6,19 66.6,22.34 64.39,24.55 64.39,31.24 64.77,31.62 64.77,36.2 65,36.42 65,38.61 64,39.61 64,56.7 60.2,60.5 v59.45,60.5
  Bottom 0.25: v59.45,60.5 59.45,62.15 60.3,63 U2.127
  Bottom 0.4: U4.33 67.5,18.5 67.15,18.85 v66.45,18.85
A9  (via drill 0.4)
  Route2 0.25: v66.7,15.65 66.7,17 67.2,17.5 67.2,22.44 64.9,24.75 64.9,30.99 65.28,31.37 65.28,35.94 65.5,36.16 65.5,38.81 64.5,39.81 64.5,57 62,59.5 v62,60.4
  Bottom 0.25: v62,60.4 62.3,60.7 U2.131
  Bottom 0.4: U4.34 68.3,16.25 67.7,15.65 v66.7,15.65
A10  (via drill 0.4)
  Route2 0.25: v68.1,9.8 69.5,11.2 69.5,14 68.5,15 68.5,16.7 68.7,16.9 68.7,26.6 68.23,27.07 68.23,28.4 65.79,30.85 65.79,35.69 66,35.9 66,39.01 65,40.01 v65,58.2
  Bottom 0.25: v65,58.2 63.8,59.4 63.8,62.65 64.3,63.15 U2.135
  Bottom 0.4: U4.22 67.5,9.2 v68.1,9.8
A11  (via drill 0.4)
  Route2 0.25: v69.28,15.65 69.2,15.72 69.2,26.8 68.73,27.27 68.73,28.6 66.29,31.04 66.29,35.43 66.5,35.64 66.5,39.21 65.5,40.21 65.5,56.75 69.47,60.73 v69.47,60.83
  Bottom 0.25: U2.145 69.3,61 v69.47,60.83
  Bottom 0.4: U4.35 69.1,15.82 v69.28,15.65
A12  (via drill 0.4)
  Route2 0.25: v73.08,18.98 74,19.9 74,28.1 73.33,28.77 73.33,30.3 71.6,32.03 71.6,33.52 70.93,34.2 70.93,38.28 68,41.21 68,54.73 v68.9,55.62
  Bottom 0.25: v68.9,55.62 69.22,55.62 71.1,57.5 71.1,61.6 71.3,61.8 U2.149
  Bottom 0.4: U4.36 69.9,18.6 70.28,18.98 v73.08,18.98
A13  (via drill 0.4)
  Route2 0.25: v69.6,9.8 70,10.2 70,16 69.7,16.3 69.7,27 69.23,27.46 69.23,28.8 66.81,31.23 66.81,35.19 66.99,35.37 66.99,39.42 66,40.41 66,56.5 69.6,60.1 73.1,60.1 v73.88,60.88
  Bottom 0.25: v73.88,60.88 74.3,61.3 U2.155
  Bottom 0.4: U4.20 69.1,7.7 69.6,8.2 v69.6,9.8
A14  (via drill 0.4)
  Route2 0.25: v68.8,9 70,9 70.5,9.5 70.5,16.2 70.2,16.5 70.2,27.2 69.73,27.66 69.73,29 67.31,31.43 67.31,34.92 67.5,35.12 67.5,39.61 66.5,40.61 66.5,56.3 69.55,59.35 v72.47,59.35
  Bottom 0.25: v72.47,59.35 75.45,59.35 76,59.9 76,60.6 76.2,60.8 U2.159
  Bottom 0.4: U4.21 68.3,7.9 68.8,8.4 v68.8,9
ACC_INT  (via drill 0.4, 0.6)
  Top 0.25: v55.9,65.55 57.15,66.8 82.3,66.8 v82.42,66.67 82.55,66.8 89.9,66.8 91.2,65.5 v91.2,65.2 | v99.99,13.67 100.8,14.48 103.12,14.48 105.56,12.04 110.9,12.04
  Top 0.4: 110.9,12.04 v113.1,12.04
  Route2 0.25: v91.2,65.2 91.2,62.9 97.2,56.9 97.2,38.9 97.7,38.4 97.7,30 98.1,29.6 98.1,23.1 99.82,21.38 99.82,18.16 100.71,17.27 100.71,14.39 v99.99,13.67
  Bottom 0.25: U2.120 56.8,64.65 v55.9,65.55 | U3.4 82.8,64.9 82.42,65.28 v82.42,66.67
  Bottom 0.6: v113.1,12.04 EXT2.33
CASN  (via drill 0.4)
  Route2 0.25: v67.4,10.6 66.9,10.6 60.4,17.1 60.4,21.3 59,22.7 59,40.5 57.1,42.4 57.1,46 55.4,47.7 v55.4,49.67
  Bottom 0.25: v55.4,49.67 51.77,53.3 U2.87
  Bottom 0.4: U4.17 71.5,9.2 70.1,10.6 v67.4,10.6
D0  (via drill 0.4)
  Route2 0.25: v84.45,10.28 84.45,11.78 89.3,16.63 89.3,25.1 86.5,27.9 86.5,30.3 86.9,30.7 86.9,38.8 86.67,39.02 v86.67,39.95
  Bottom 0.25: U2.197 78,41.8 80.1,39.7 81.1,39.7 82.1,40.7 86.4,40.7 86.67,40.42 v86.67,39.95
  Bottom 0.4: v84.45,10.28 84.45,10.15 83.5,9.21 U4.2
D1  (via drill 0.4)
  Route2 0.25: v85.67,39.95 85.67,39.12 86.4,38.4 86.4,31 86,30.6 86,27.72 88.8,24.92 88.8,16.96 83.31,11.47 v83.31,10.29
  Bottom 0.25: v85.67,39.95 85.67,38.88 84.3,37.5 80.2,37.5 77.9,39.8 U2.201
  Bottom 0.4: U4.4 81.9,8.88 v83.31,10.29
D2  (via drill 0.4)
  Route2 0.25: v82.13,10.33 82.13,11.11 88.3,17.28 88.3,24.73 85.5,27.53 85.5,32.88 v85.65,33.02
  Bottom 0.25: v85.65,33.02 84.88,33.02 84.3,33.6 84.3,33.8 81.6,36.5 79.7,36.5 79.4,36.8 U2.207
  Bottom 0.4: U4.5 81.1,9.3 v82.13,10.33
D3  (via drill 0.4)
  Route2 0.25: v75.1,12.2 75,12.3 75,28.55 74.33,29.22 74.33,31 72.9,32.43 v72.9,32.65
  Bottom 0.25: v72.9,32.65 73,32.65 73.8,33.45 U2.3
  Bottom 0.4: U4.7 79.5,7.2 75.1,11.6 v75.1,12.2
D4  (via drill 0.4)
  Route2 0.25: v68.86,36.01 68.71,35.85 68.71,34.8 68.33,34.42 68.33,31.81 70.73,29.4 70.73,28.07 71.2,27.6 71.2,16.94 73.3,14.84 v73.3,12.4
  Bottom 0.25: v68.86,36.01 68.8,35.95 U2.13 68.8,33.99
  Bottom 0.4: U4.8 78.7,7 v73.3,12.4
D5  (via drill 0.4)
  Route2 0.25: v72.3,12.95 72.3,15.15 70.7,16.75 70.7,27.4 70.23,27.86 70.23,29.2 67.85,31.59 67.85,34.7 68.01,34.86 68.01,36.84 v68.28,37.11
  Bottom 0.25: v68.28,37.11 68,37.11 66.8,35.91 U2.17
  Bottom 0.4: U4.10 77.1,7.45 72.3,12.25 v72.3,12.95
D6  (via drill 0.4)
  Route2 0.25: v68.78,12.03 68.78,13.72 68,14.5 68,16.9 68.2,17.1 68.2,25.26 66.47,26.99 66.47,28.41 66.07,28.81 v65.92,28.81
  Bottom 0.25: v65.92,28.81 v65.91,28.81 65.91,30.35 63.8,32.47 U2.23
  Bottom 0.4: U4.11 76.3,7.3 71.58,12.03 v68.78,12.03
D7  (via drill 0.4)
  Route2 0.25: v67.8,11.6 67.8,13.9 67.5,14.2 67.5,17.1 67.7,17.3 67.7,24.93 65.67,26.96 v65.67,27.71
  Bottom 0.25: v65.67,27.71 65.12,28.25 65.12,30.35 63.67,31.8 62.02,31.8 61.67,32.15 61.67,33.05 61.8,33.17 U2.27
  Bottom 0.4: U4.13 74.7,7 70.5,11.2 68.2,11.2 v67.8,11.6
D8  (via drill 0.4)
  Route2 0.25: v85.5,11.18 85.5,12 89.86,16.36 89.86,26.48 89,27.34 89,29.9 88.9,30 v88.9,42.4
  Bottom 0.25: v88.9,42.4 88.6,42.7 80.6,42.7 78.5,44.8 U2.191
  Bottom 0.4: U4.42 74.7,15.46 78.99,11.18 v85.5,11.18
D9  (via drill 0.4)
  Route2 0.25: v72.15,41.43 72.15,41.26 76.8,36.61 76.8,31.7 76.4,31.3 76.4,29.95 77,29.35 77,27.25 79.18,25.07 79.18,23.18 80.83,21.53 80.83,20.76 80.26,20.19 80.26,16.94 81.1,16.1 81.1,12.9 v80.4,12.2
  Bottom 0.25: v72.15,41.43 72.15,41.26 73.31,40.1 75.5,40.1 76.2,40.8 U2.199
  Bottom 0.4: v80.4,12.2 79.6,12.2 76.3,15.5 U4.44
D10  (via drill 0.4)
  Route2 0.25: v85.17,33.92 84.9,33.65 84.9,32.73 85,32.62 85,27.35 87.8,24.55 87.8,17.95 v84.96,15.11
  Bottom 0.25: v85.17,33.92 82.1,37 80,37 79.2,37.8 U2.205
  Bottom 0.4: U4.45 77.1,15.6 78.2,14.5 84.35,14.5 v84.96,15.11
D11  (via drill 0.4)
  Route2 0.25: v79.28,19 79.28,20.62 76.5,23.39 76.5,29.15 75.9,29.75 75.9,31.6 76.3,32 76.3,35.02 v76.08,35.25
  Bottom 0.25: v76.08,35.25 76.08,35.8 76.58,36.3 U2.208
  Bottom 0.4: U4.47 78.7,18.43 v79.28,19
D12  (via drill 0.4)
  Route2 0.25: v75.03,35.23 74.8,35 74.8,29.46 75.5,28.77 75.5,21.19 77.3,19.39 77.3,16.6 v78.6,15.3
  Bottom 0.25: v75.03,35.23 74.8,35 U2.1
  Bottom 0.4: v78.6,15.3 79.5,16.2 U4.48
D13  (via drill 0.4)
  Route2 0.25: v80.3,15.3 80.3,16.2 78.5,18 78.5,20.59 76,23.09 76,28.95 75.4,29.55 75.4,32 75.55,32.15 v75.55,32.58
  Bottom 0.25: 80.3,15.4 v80.3,15.3 | v75.55,32.58 74.85,31.88 72.62,31.88 72.14,32.36 72.14,33.02 71.8,33.36 U2.7
  Bottom 0.4: U4.50 81.1,16.2 80.3,15.4
D14  (via drill 0.4)
  Top 0.25: v80.14,24.51 80.14,26.67 78.23,28.57 67.82,28.57 v67.31,28.07
  Route2 0.25: v80.14,24.51 79.76,24.13 79.76,23.37 81.53,21.59 82.04,21.59 82.66,20.97 82.66,18.15 81.9,17.38 v81.9,15.3
  Bottom 0.25: v67.31,28.07 67.31,30.1 64.8,32.61 U2.21
  Bottom 0.4: v81.9,15.3 U4.51
D15  (via drill 0.4)
  Top 0.25: v80.64,23.62 79.88,23.62 79.63,23.88 78.49,23.88 77.6,22.99 74.17,22.99 73.91,23.24 72.14,23.24 70.99,24.38 66.55,24.38 v65.91,25.02
  Route2 0.25: v84.14,15.97 84.45,16.29 84.45,20.26 84.01,20.7 83.69,20.7 80.77,23.62 v80.64,23.62
  Bottom 0.25: U2.28 61.3,33.36 61.17,33.23 61.17,31.82 61.79,31.2 63.45,31.2 64.62,30.03 64.62,26.31 v65.91,25.02
  Bottom 0.4: U4.53 83.5,16.45 83.98,15.97 v84.14,15.97
D+  (via drill 0.5)
  Top 0.4: v18.9,51.5 v18.9,56.8
  Bottom 0.4: R30.1 18.5,49.6 18.5,51.1 v18.9,51.5
  Bottom 0.5: USB.D+ 17.2,57.5 R34.1
  Bottom 0.6: v18.9,56.8 R34.1
D-
  Bottom 0.5: USB.D- 16.4,57.4 R33.1
DBGEN
  Bottom 0.25: R44.1 92.3,36.1 92.3,31.7 91.23,30.63 89.67,30.63 88.7,31.6 85.53,31.6 83.8,33.33 83.8,33.5 81.4,35.9 78.9,35.9 76.4,33.4 76.4,32.2 75.6,31.4 72.4,31.4 71.63,32.17 71.63,32.58 70.8,33.4 U2.9
DISP  (via drill 0.4)
  Route2 0.25: v82.45,31.27 82.45,31.57 80.8,33.23 80.8,38.3 78.2,40.9 78.2,56.9 v74.78,60.33
  Bottom 0.25: LCD.31 76,27.8 77,28.8 79.97,28.8 v82.45,31.27 | v74.78,60.33 74.55,60.1 73.6,60.1 73.15,60.55 73.15,61.55 73.8,62.2 U2.154
DQMN0  (via drill 0.4)
  Route2 0.25: v66.3,4.1 65.1,5.3 64.6,5.3 56.8,13.1 51.7,13.1 50.05,14.75 v50.05,30.5
  Bottom 0.25: v50.05,30.5 50.05,30.65 50.8,31.4 U2.49
  Bottom 0.4: U4.15 73.1,4.6 72.8,4.3 71.9,4.3 70.9,3.3 67.1,3.3 v66.3,4.1
DQMN1  (via drill 0.4)
  Top 0.25: v52.5,16 53.3,16 54.4,14.9 69.3,14.9 70.5,13.7 v71.5,13.7
  Route2 0.25: v52.7,36.25 52.4,36.25 51.9,35.75 51.9,32.9 52.9,31.9 52.9,16.4 v52.5,16
  Bottom 0.25: v52.7,36.25 52.98,36.25 53.5,35.73 53.5,35.05 53.8,34.75 U2.43
  Bottom 0.4: v71.5,13.7 72.3,14.5 U4.39
GND  (via drill 0.4, 0.6, 1)
  Top 0.4: v90.1,65.17 77.12,65.17 v76.92,65.38 | v95.38,27.81 94.99,27.81 92.22,30.57 86.08,30.57 83.75,32.9 v82.95,32.9
  Top 0.6: v83.8,50.75 v95.3,50.75 | v97.42,62.15 97.88,61.7 106.1,61.7 | 106.1,61.7 GND.P$1 | v91.6,22.3 81.74,22.3 80.16,20.72 v77.15,20.72 77.13,20.7 73.05,20.7 v72.77,20.97 | v113.3,59.37 113.3,59.55 111.15,61.7 106.1,61.7
  Top 0.8: 11.6,52.8 v3.7,52.8 | 11.6,52.8 v11.6,54.2 | 11.6,52.8 13.6,52.8 16,50.4 v23.7,50.4 26,52.7 38.3,52.7 v39.6,54
  Route2 0.25: v82.7,2.6 81.11,4.19 81.11,11.49 82.9,13.28 v82.9,15.3
  Route2 0.4: v77.15,20.72 77.9,19.96 77.9,17.6 79.4,16.1 79.4,8.1 77.3,6 v77.3,4.1 | v113.3,56.83 112.97,56.83 112.3,57.5 112.3,58.6 113.06,59.37 v113.3,59.37
  Route2 0.6: 83.8,45.42 v83.8,50.75 83.8,56.75 v83.9,56.85 | 83.8,45.42 v83.6,45.42 | 83.8,39.95 83.8,45.42 | v39.5,48.2 39.6,48.3 v39.6,54 | v41.7,29.93 41.1,30.52 41.1,35.3 40.6,35.8 v40.6,41.35 | v95.3,50.75 95.3,51.5 92.6,54.2 92.6,59.98 90.1,62.48 v90.1,65.17 | v95.38,27.81 95.3,27.89 v95.3,32.85 | v82.95,32.9 83.25,33.2 83.25,38.15 83.8,38.7 83.8,39.95 | 83.8,39.95 v83.7,39.95
  Route2 0.8: v24.7,31 24.7,36.8 | 24.7,36.8 24.7,49.3 23.7,50.3 v23.7,50.4 v23.7,56.85 | 24.7,36.8 v23.1,36.8
  Bottom 0.25: U2.114 53.8,64.9 52.3,66.4 48,66.4 47.8,66.2 | U2.148 70.8,65.17 70.7,65.28 C26.1 | U2.169 79,55.8 79.8,55 83.02,55 83.5,55.48 83.5,55.5 C27.1 v83.9,56.85 | C36.1 83.5,52.3 83.5,52.5 82.2,53.8 79.3,53.8 78.8,54.3 U2.172 | U2.189 78.9,45.8 80.9,43.8 82.9,43.8 84.3,45.2 84.3,46 C28.1 83.6,46.1 v83.6,45.42 | U2.200 78.1,40.3 80.4,38 83.4,38 83.6,38.2 83.6,38.7 C29.1 | U2.84 45.7,51.8 42.8,48.9 42.8,48.4 42.3,47.9 41.1,47.9 C35.1 | U2.63 44.9,41.3 42.8,39.2 40.6,39.2 40.33,38.92 40.33,38.73 C20.1 | U2.93 42.3,56.3 40.4,54.4 40.4,53.5 C22.1 | 87.78,64.97 87.7,64.9 U3.7 85.7,64.9 85.2,64.4 U3.3 | U4.12 75.5,5.1 76.5,4.1 76.5,2.4 76.28,2.17 75.88,2.17 C41.1 | C42.1 77.9,19.8 U4.46 | U2.33 58.8,32.5 59,32.3 | U2.32 59.3,33.1 60,32.4 | 39.5,46.1 43,46.1 43.4,45.7 44.4,45.7 45.9,47.2 45.9,48 46.2,48.3 U2.77 | 61.2,66.9 C25.1 61.9,65.1 63.1,65.1 63.3,64.9 U2.133 | LCD.36 73.5,25.43 74.38,24.55 74.38,20.68 C52.1 | v77.15,20.72 76.5,21.36 76.5,25.05 77,25.55 LCD.29 | v95.3,32.85 94.6,33.55 94.6,34.9 C3.1 | 91.08,24.35 91,24.43 LCD.1 | LCD.3 90,22.7 89.7,22.4 89.7,20.28 90.08,19.9 | C39.1 81.56,1.8 82.36,2.6 v82.7,2.6
  Bottom 0.4: v113.3,56.83 EXT1.5 | v113.3,59.37 EXT1.1 | 63.1,17.5 U4.28 | RM1.4.1 40.36,55.86 39.6,55.1 v39.6,54 39.6,53.5 C22.1 | 47.8,66.2 47.2,65.6 46.1,65.6 C23.1 45.8,66 46.7,66.9 61.2,66.9 70.1,66.9 70.4,66.6 70.4,65.9 C26.1 | 87.78,64.97 88.72,64.97 C18.1 89.08,65.17 v90.1,65.17 | C52.1 U4.41 | v82.9,15.3 82.7,15.5 U4.52 | 59,32.3 59,27.1 59.2,26.9 60,26.9 60.4,26.5 | R15.1 92.3,49.5 T2.2 94.61,49.91 95.3,49.91 | 53.7,24.2 53.3,24.6 53.3,26.5 54.2,27.4 54.2,32.4 | 60,32.4 C30.1 60.3,31 61.1,31 61.6,30.5 63.23,30.5 63.95,29.78 63.95,26.85 63.6,26.5 60.4,26.5 | 60.4,24.3 60.4,26.5 | 98.7,29.35 98.7,31.2 99,31.5 104.9,31.5 105.31,31.09 | 91.08,24.35 91.08,22.82 v91.6,22.3 91.57,22.27 91.57,20.77 R9.1 90.08,19.9 | C38.1 79.52,1.8 80.3,2.58 U4.6 | C42.1 78.1,20.2 77.58,20.72 v77.15,20.72 | U4.54 84.3,17.3 86.85,14.75 MICRO_SD.11 | v77.3,4.1 77.3,0.93 77.34,0.89 | R38.2 97.88,49.91 95.3,49.91 | v95.3,50.75 95.3,49.91
  Bottom 0.406: C17.1 80.7,33.85 81.65,32.9 v82.95,32.9
  Bottom 0.5: USB.GND 18.8,58.8 20.2,57.4 | 39.5,41.22 RM2.3.1 | 39.5,40.33 RM2.4.1
  Bottom 0.508: MICRO_SD.6 97.23,13.77 v97.28,13.72
  Bottom 0.559: U5.2 46.61,3.81 47.46,4.66 R29.1 | VR2.5 17.78,21.72 17.53,21.72
  Bottom 0.6: 62.4,15.6 63.1,16.3 63.1,17.5 63.1,18.1 62.6,18.1 61.7,19 R21.2 61,19.2 61,20.43 59,22.43 | 62.4,15.6 T4.2 | Q2.GND 59,22.43 | 39.5,40.35 39.5,40.33 | 11.6,55.1 13.3,56.8 C11.2 | v11.6,54.2 11.6,55.1 | 11.6,55.1 C13.1 | v83.8,50.75 83.8,51.8 C36.1 | v83.7,39.95 83.7,39.2 C29.1 | v76.92,65.38 75.6,66.7 72.2,66.7 71.1,65.6 C26.1 | 62.4,15.6 62.4,12.8 61.7,12.1 60.1,12.1 59.7,11.7 C40.1 59.7,7.36 v59.94,7.11 60.4,6.66 C9.1 | EXT2.1 109.67,32.37 108.39,31.09 EXT2.4 105.31,31.09 | 39.5,43.3 39.5,46.1 v39.5,48.2 39.5,48.5 C35.1 | v95.38,27.81 95.38,23.98 93.7,22.3 v91.6,22.3 | v97.42,62.15 98.25,62.15 C8.1 97.8,61.9 97.8,60.64 RESET.P$2 93.5,56.34 93.5,53.19 93.94,52.74 C50.1 | C14.1 43,28.8 41.88,29.93 v41.7,29.93 | 39.5,43.3 39.5,41.35 | 39.5,43.3 C21.1 | C16.1 54.1,24.2 53.7,24.2 | 59,22.43 C15.1 60.1,24 60.4,24.3 | R55.2 41.4,26.7 C12.1 | C52.1 73.78,20.2 73.01,20.97 v72.77,20.97
  Bottom 0.711: MICRO_SD.9 100.53,14.99 101.73,14.99 MICRO_SD.10
  Bottom 0.762: MICRO_SD.12 101.73,1.14 101.98,0.89
  Bottom 0.8: 18.58,29.3 13.4,29.3 C46.- 9.5,29.4 7.64,31.26 G1.- 7.64,34.06 8.62,35.04 C31.2 | C14.1 C12.1 43.3,24.3 45.5,22.1 45.5,16.5 50,16.5 50.9,17.4 50.9,20.52 52.8,22.43 54.3,22.43 | 54.3,22.43 Q2.GND | 54.3,22.43 C16.1 | 24.77,30.1 24.7,30.1 v24.7,31 | 24.77,30.1 C33.- | JTAG.4 29.4,59.39 29.4,56.85 | 29.4,56.85 JTAG.6 v23.7,56.85 20.2,56.85 | 29.4,56.85 29.4,54.31 | 29.4,54.31 JTAG.8 | 29.4,51.77 29.4,54.31 | JTAG.10 29.4,51.77 | 29.4,51.77 29.4,49.23 | JTAG.12 29.4,49.23 | 29.4,49.23 29.4,46.69 | 29.4,46.69 JTAG.14 | 29.4,46.69 29.4,44.15 | 29.4,44.15 JTAG.16 | 29.4,44.15 29.4,41.61 | 29.4,41.61 JTAG.18 21.99,41.61 21.8,41.8 R35.2 | JTAG.20 29.4,39.07 29.4,41.61 | 20.2,56.85 20.2,57.4 | 20.2,56.85 C10.2 | v23.1,36.8 R45.1 | C37.1 83.86,1.82 83.86,0.97 83.95,0.89 | C4.1 20.07,29.34 20.03,29.3 18.58,29.3 | 18.58,29.3 21.93,29.3 22.74,30.11 C34.1 24.77,30.1 | 78.49,1.78 78.5,1.78 C38.1 | 78.49,1.78 | 81.53,1.78 81.5,1.78 C39.1 81.5,0.92 81.53,0.89 | BUT.P$2 72.66,0.89 75.44,0.89 | 86.23,1.14 85.98,0.89 83.95,0.89 | 75.44,0.89 77.34,0.89 78.49,0.89 | 78.49,0.89 81.53,0.89 | 81.53,0.89 83.95,0.89 | 78.49,0.89 78.49,1.78 | C41.1 75.5,0.95 75.44,0.89 | C6.1 98.68,28.45 98.7,28.45 98.7,29.35 98.58,29.46 95.63,29.46 C2.2 95.38,29.21 v95.38,27.81
  Bottom 0.889: MICRO_SD.10 101.73,13.72 v101.35,13.34
  Bottom 1: 45.5,16.5 v43.49,16.5 | C20.1 39.5,38.7 39.5,40.35 39.5,41.22 39.5,41.35 v40.6,41.35 | UEXT.2 3.7,51.58 v3.7,52.8 | JTAG.12 24.17,49.23 23.7,49.7 v23.7,50.4 23.7,51.4 24.07,51.77 JTAG.10
  Bottom 1.016: C5.2 41.54,1.64 42.16,1.02 v43.19,1.02 | 49.15,4.7 48.51,4.7 48.51,4.66 R29.1 47.88,5.08 | 47.88,5.08 v47.88,6.1 v49.15,6.1 49.15,5.08 | 49.15,5.08 49.15,4.7 | 49.15,4.7 C7.2 | 47.88,5.08 49.15,5.08 | MICRO_SD.11 87.63,14.25 v87.63,12.7 v87.63,11.68 87.63,9.78 | 87.63,9.78 v87.63,10.67 | 87.63,9.78 87.63,7.75 86.23,6.35 MICRO_SD.13 86.23,1.14 86.23,0.89 101.98,0.89 103.48,0.89 | 103.48,0.89 SD.C | 103.48,0.89 105.28,0.89 105.92,1.52 R16.1 | 20.07,12.48 R22.1 | C48.2 20.07,12.48 | 20.07,12.48 v20.07,11.05 | 14.99,15.53 14.31,15.53 v14.22,15.62 | 14.99,15.53 R54.1 | R52.1 14.99,15.53 | v16.26,21.08 16.26,21.72 17.02,21.72 | 17.02,21.72 17.53,21.72 | R28.1 17.11,25.36 16.38,24.64 16.38,22.1 16.73,21.76 17.06,21.76 17.02,21.72
  Bottom 1.27: C24.2 22.48,25.65 | 22.48,25.65 C47.2 22.48,26.16 v24.51,26.16 25.4,26.16 | 30.52,21.97 C32.1 | 30.52,21.97 C45.1 29.25,24.13 26.07,24.13 D6.2 26.04,24.26 | 30.52,21.97 30.52,22.48 | 26.04,26.16 25.4,26.16 | 26.67,26.16 v26.16,26.16 26.04,26.16 | 26.67,26.16 v27.81,26.16 | 26.04,25.65 26.04,26.16 | 26.04,25.65 26.04,24.26 | 25.4,26.16 25.4,24.26 26.04,24.26 | 26.04,24.26 26.67,24.26 26.67,26.16 | 22.48,25.65 26.04,25.65
  other vias: 77.6,10.8 24.3,65.7 62.15,42.75 33.66,7.24 28.96,21.84
  pour Top (isolate 0.406, rank 6): -2,69.5 117,69.5 117,-2 -2,-2
  pour Bottom (isolate 0.406, rank 6): -5,72.5 119.87,72.5 119.87,-5 -5,-5
  pour Route15 (isolate 0.406, rank 6): -4,71.5 119,71.5 119,-4 -4,-4
GNDA  (via drill 0.4)
  Top 0.25: v63.5,35.75 60.75,38.5 57.4,38.5 55.6,36.7 55,36.7 54.24,35.94 54.24,33.04 53.1,31.9 41.3,31.9 v39.5,30.1
  Route2 0.25: v63.5,35.75 63.75,35.51 63.75,32.12 63.37,31.75 63.37,23.75 64,23.12 v64,21.4
  Bottom 0.25: v64,21.4 63.9,21.3 63.9,20.6 C44.1 | v63.5,35.75 63.6,35.75 64.3,35.05 U2.22
  Bottom 0.4: 39.5,28.5 v39.5,30.1 | C19.1 39.5,28.5 | 39.5,28.5 R55.1
ISP_E  (via drill 0.4)
  Route2 0.25: v64.6,4.1 56.2,12.5 51.4,12.5 48.9,15 48.9,35.1 49.7,35.9 49.7,40.5 48,42.2 48,56.23 v51.95,60.17
  Bottom 0.25: v51.95,60.17 51.55,60.58 51.55,63.05 51.8,63.3 U2.110 | BUT.P$1 64.6,2.76
  Bottom 0.6: BUT.P$1 63.61,1.77 62.77,1.77 R24.1 C9.2 | 64.6,2.76 v64.6,4.1
LCD0  (via drill 0.4)
  Route2 0.25: v73.15,56.85 73.15,54.05 72.5,53.4 72.5,45.9 72.9,45.5 73.9,45.5 75.7,43.7 75.7,39.9 78.3,37.3 78.3,32.35 79.7,30.95 79.7,29.55 81.3,27.95 81.3,27 82.3,26 83.6,26 85.8,23.8 85.8,21.54 85.05,20.79 85.05,18.07 v85.34,17.78
  Bottom 0.25: U2.168 76.33,56.3 75.62,55.6 73.6,55.6 73.15,56.05 v73.15,56.85 | LCD.5 89,19.6 87.18,17.78 v85.34,17.78
LCD1  (via drill 0.4)
  Route2 0.25: v75.15,56.83 75.15,55.65 77.2,53.6 77.2,40.5 79.8,37.9 79.8,32.85 81.2,31.45 81.2,30.2 84,27.4 84,26.95 86.8,24.15 86.8,21.14 86.17,20.51 86.17,19.82 86.87,19.12 v86.87,18.54
  Bottom 0.25: LCD.6 88.5,19.9 87.14,18.54 v86.87,18.54 | v75.15,56.83 75.15,56.85 75.6,57.3 U2.166
LCD2  (via drill 0.4)
  Route2 0.25: v85.83,18.82 85.66,18.99 85.66,20.7 86.3,21.34 86.3,24 83.8,26.5 82.5,26.5 81.75,27.25 81.75,28.25 80.2,29.8 80.2,31.15 78.8,32.55 78.8,37.5 76.2,40.1 76.2,48.8 74.5,50.5 v74.5,51.45
  Bottom 0.25: v85.83,18.82 85.83,18.9 86.31,19.38 87.23,19.38 88,20.15 LCD.7 | U2.170 76.2,55.3 74.5,53.6 v74.5,51.45
LCD3  (via drill 0.4)
  Route2 0.25: v86.95,20.22 87.3,20.57 87.3,24.35 84.5,27.15 84.5,32.45 84.4,32.55 84.4,37.6 84.95,38.15 84.95,41.85 86.7,43.6 v86.7,47.38
  Bottom 0.25: v86.7,47.38 86.7,48.6 85.8,49.5 82.2,49.5 79.4,52.3 U2.176 | v86.95,20.22 87.5,20.77 LCD.8
LCD4  (via drill 0.4)
  Route2 0.25: v88.28,27.9 88.5,28.12 88.5,29.7 88.4,29.8 88.4,41.6 88.1,41.9 88.1,42.7 89.5,44.1 89.5,48.9 86.7,51.7 86.7,58.4 80.1,65 79.4,65 77.8,63.4 66.95,63.4 v65.58,62.02
  Bottom 0.25: LCD.9 87,27.1 87.2,27.3 87.67,27.3 v88.28,27.9 | v65.58,62.02 65.8,62.25 U2.138
LCD5  (via drill 0.4)
  Top 0.25: v84.92,56.88 84.2,57.6 71.65,57.6 70.65,58.6 v66,58.6
  Route2 0.25: v87.3,28.2 87,28.5 87,30 87.4,30.4 87.4,41.2 87.1,41.5 87.1,43.3 88.53,44.73 88.53,48.38 84.92,51.98 v84.92,56.88
  Bottom 0.25: LCD.10 86.5,27.65 87.05,28.2 v87.3,28.2 | U2.136 64.8,62.98 64.3,62.48 64.3,60.3 v66,58.6
LCD6  (via drill 0.4)
  Route2 0.25: v84.5,21.34 83.95,21.34 82.3,22.99 82.3,24.46 80.3,26.46 80.3,27.6 78.7,29.2 78.7,30.55 77.3,31.95 77.3,36.9 73.5,40.7 73.5,41.2 71.5,43.2 71.5,55.5 v71.42,55.58
  Bottom 0.25: U2.134 63.8,63.3 63.3,62.8 63.3,58.8 67.2,54.9 70.75,54.9 v71.42,55.58 | LCD.11 86,22.5 84.84,21.34 v84.5,21.34
LCD7  (via drill 0.4)
  Route2 0.25: v84.81,23.2 84.24,23.2 80.8,26.64 80.8,27.75 79.2,29.35 79.2,30.75 77.8,32.15 77.8,37.1 74,40.9 74,41.4 72,43.4 72,54.48 72.3,54.77 v72.3,56.27
  Bottom 0.25: U2.132 62.8,58.6 67,54.4 71.5,54.4 72.3,55.2 v72.3,56.27 | LCD.12 85.5,23.5 85.2,23.2 v84.81,23.2
LCD8  (via drill 0.4)
  Route2 0.25: v85.95,56.9 85.95,51.75 89,48.7 89,44.4 87.6,43 87.6,41.7 87.9,41.4 87.9,29.25 v87.75,29.1
  Bottom 0.25: U2.164 78.1,58.3 78.8,57.6 85.25,57.6 v85.95,56.9 | LCD.13 85,27.4 86.7,29.1 v87.75,29.1
LCD9  (via drill 0.4)
  Route2 0.25: v90.22,28.05 91.2,28.05 92,28.85 92,49.2 89,52.2 v89,58.35
  Bottom 0.25: U2.162 78.5,59.3 79.2,58.6 86.3,58.6 86.8,58.1 88.75,58.1 v89,58.35 | LCD.14 84.5,27.6 86.8,29.9 88.3,29.9 90.15,28.05 v90.22,28.05
LCD10  (via drill 0.4)
  Top 0.25: v51.1,30.6 53.21,30.6 53.85,31.24 71.5,31.24 72.01,30.73 76.83,30.73 83.34,24.23 v84.33,24.23
  Route2 0.25: v51.1,30.6 51.1,31.6 50.2,32.5 v50.2,43.5
  Bottom 0.25: v84.33,24.23 84,24.55 LCD.15 | v50.2,43.5 48.9,44.8 U2.70
LCD11  (via drill 0.4)
  Top 0.25: v83.66,19.91 83.64,19.94 83.44,19.94 82.68,19.18 82.68,18.17 81.71,17.2 72.3,17.2 69.9,19.6 64.2,19.6 63.6,19 59,19 57.7,20.3 42.8,20.3 v42.1,21
  Route2 0.25: v42.5,44.65 43.5,43.65 43.5,39.4 42.5,38.4 42.5,31.8 43,31.3 43,22.3 42.1,21.4 v42.1,21
  Bottom 0.25: v42.5,44.65 44.77,44.65 45.92,45.8 U2.72 | LCD.16 83.5,23.94 83.95,23.5 83.95,22.86 83.44,22.35 83.44,20.14 v83.66,19.91
LCD12  (via drill 0.4)
  Top 0.25: v40.3,25.15 64,25.15 65.34,23.82 70.73,23.82 71.8,22.75 73.65,22.75 73.91,22.48 77.73,22.48 78.58,23.33 79.16,23.33 79.73,22.76 81.18,22.76 81.66,23.24 v83.12,23.24
  Route2 0.25: v40.3,25.15 40.3,35 39.77,35.52 39.77,44.02 v40.4,44.65
  Bottom 0.25: v40.4,44.65 41.25,45.5 42.9,45.5 43.2,45.2 44.6,45.2 46.2,46.8 U2.74 | LCD.17 83,23.36 v83.12,23.24
LCD13  (via drill 0.4)
  Route2 0.25: v82.5,27.55 82.5,28.25 80.7,30.05 80.7,31.3 79.3,32.7 79.3,37.7 76.7,40.3 76.7,49.45 v75.3,50.85
  Bottom 0.25: U2.76 55,47.8 58.2,51 73.75,51 74.05,50.7 75.15,50.7 v75.3,50.85 | v82.5,27.55 LCD.18
LCD14  (via drill 0.4, 0.6)
  Top 0.25: v30.8,45.4 34.67,45.4 35.17,45.9 43.5,45.9 v44.05,46.45 | v37.1,20.8 40.9,20.8 42.9,18.8 57.6,18.8 58.4,18 70.8,18 72.1,16.7 81.98,16.7 83.58,18.3 v83.58,18.86
  Route2 0.25: v30.8,45.4 31.6,44.6 31.6,26.3 v37.1,20.8
  Bottom 0.25: v44.05,46.45 44.25,46.45 45.4,47.6 45.4,48.2 46,48.8 U2.78 | LCD.19 82,25.44 82.36,25.08 82.36,22.86 82.93,22.29 82.93,19.51 v83.58,18.86
LCD15  (via drill 0.4, 0.6)
  Top 0.25: v81.41,18.9 80.7,18.2 72.7,18.2 70.3,20.6 63.4,20.6 62.5,21.5 60.4,21.5 59.6,22.3 v36.7,22.3 | v44.6,48.2 43.8,48.2 42.5,46.9 32.05,46.9 v31,47.95
  Route2 0.25: v31,47.95 31,47.2 32.1,46.1 32.1,26.9 v36.7,22.3
  Bottom 0.25: LCD.20 81.5,25.18 81.88,24.8 81.88,22.54 82.46,21.96 82.46,19.34 82.02,18.9 v81.41,18.9 | v44.6,48.2 46.2,49.8 U2.80
LCD16  (via drill 0.4)
  Route2 0.25: v90.8,28.9 91.5,29.6 91.5,49 88.2,52.3 88.2,59.45 v88.6,59.85
  Bottom 0.25: LCD.21 81,27.2 82.1,28.3 83,28.3 83.3,28 84.2,28 86.6,30.4 88.5,30.4 90,28.9 v90.8,28.9 | v88.6,59.85 87.85,59.1 87.2,59.1 86.7,59.6 79.6,59.6 78.9,60.3 U2.160
LCD17  (via drill 0.4)
  Route2 0.25: v90.26,29.77 91,30.51 91,48.8 87.7,52.1 87.7,59.7 v87.55,59.85
  Bottom 0.25: U2.158 78.6,61.3 79.8,60.1 87.3,60.1 v87.55,59.85 | LCD.22 80.5,27.6 83.9,31 88.55,31 89.78,29.77 v90.26,29.77
LCD18  (via drill 0.4, 0.6)
  Top 0.25: v81.66,20.82 82.19,20.29 82.19,18.51 81.38,17.7 72.5,17.7 70.1,20.1 63.2,20.1 62.3,21 60.2,21 59.4,21.8 38.35,21.8 v38.1,21.55
  Route2 0.25: v38.1,21.55 38.1,22 37.1,23 37.1,25.7 34.7,28.1 34.7,32.2 33.1,33.8 33.1,49.7 35,51.6 35,59.5 38.2,62.7 v38.2,63.9
  Bottom 0.25: LCD.23 80,25.44 80.17,25.27 80.64,25.27 81.4,24.52 81.4,21.08 v81.66,20.82 | U2.106 49.8,64.7 49.62,64.88 48.67,64.88 47.1,63.3 42.1,63.3 40.6,64.8 38.8,64.8 38.2,64.2 v38.2,63.9
LCD19  (via drill 0.4, 0.6)
  Top 0.25: v77.83,27.57 76.35,27.57 75.67,26.9 37.4,26.9 36.3,28 v36.3,30 | v35.9,55.6 35.18,56.32 35.18,58.67 35.7,59.2 v42.58,59.2
  Route2 0.25: v35.9,55.6 35.9,52 36.62,51.27 36.62,45.17 37.3,44.5 37.3,43.2 36,41.9 36,35 36.3,34.7 v36.3,30
  Bottom 0.25: LCD.24 79.5,27.1 79.03,27.57 v77.83,27.57 | v42.58,59.2 43.9,59.2 45.5,60.8 U2.102
LCD20  (via drill 0.4, 0.6)
  Top 0.25: v79.57,21.65 79.38,21.46 73.39,21.46 73.14,21.72 71.43,21.72 70.37,22.78 64.85,22.78 63.83,23.8 37,23.8 v34.2,26.6 | v44.3,49.2 44,49.2 42.2,47.4 32.86,47.4 v32.26,48.01
  Route2 0.25: v32.26,48.01 32.6,47.66 32.6,33.5 34.2,31.9 v34.2,26.6
  Bottom 0.25: LCD.25 79,25.39 79.38,25.02 79.38,23.11 79.57,22.92 v79.57,21.65 | v44.3,49.2 45.9,50.8 U2.82
LCD21  (via drill 0.4)
  Top 0.25: v78.8,22.43 78.34,21.97 73.66,21.97 73.39,22.25 71.65,22.25 70.62,23.28 65.11,23.28 64.01,24.38 37.52,24.38 34.2,27.7 34.2,34.4 v35.1,35.3 | v44.3,52.3 43.4,51.4 40.1,51.4 39.35,50.65 39.35,50.05 38.9,49.6 37,49.6 v35.6,48.2
  Route2 0.25: v35.6,48.2 34.9,47.5 34.9,44.4 35.7,43.6 35.7,42.5 35.1,41.9 v35.1,35.3
  Bottom 0.25: LCD.26 78.5,25.13 78.87,24.77 78.87,22.5 v78.8,22.43 | v44.3,52.3 45.8,53.8 U2.88
LCD22  (via drill 0.4)
  Top 0.25: v44.75,54.8 41.85,51.9 39.9,51.9 39.4,51.4 37.5,51.4 v35.9,49.8 | v35.1,33.9 35.1,33.5 34.7,33.1 34.7,28 36.8,25.9 75.06,25.9 77.22,23.75 v77.28,23.75
  Route2 0.25: v35.1,33.9 34.1,34.9 34.1,48 v35.9,49.8
  Bottom 0.25: v44.75,54.8 U2.90 | LCD.27 78,24.41 77.34,23.75 v77.28,23.75
LCD23  (via drill 0.4)
  Top 0.25: v77.28,24.77 75.65,26.4 37.1,26.4 35.5,28 v35.5,28.8 | v43.75,55.2 40.95,52.4 39.7,52.4 39.2,51.9 36.7,51.9 v35.55,50.75
  Route2 0.25: v35.55,50.75 33.6,48.8 33.6,34.1 35.5,32.2 v35.5,28.8
  Bottom 0.25: v77.28,24.77 77.5,25 LCD.28 | v43.75,55.2 44.35,55.8 U2.92
LCD_BL  (via drill 0.4)
  Top 0.25: v71.4,56.73 69.28,54.6 56.27,54.6 v56.01,54.86
  Route2 0.25: v59.5,19.9 59.5,21.5 58.5,22.5 58.5,40.3 56.6,42.2 56.6,45.8 54.6,47.8 54.6,53.46 v56.01,54.86
  Bottom 0.25: v71.4,56.73 71.6,56.92 71.6,61.4 72.8,62.6 U2.152
  Bottom 0.6: R39.1 59.5,19.4 v59.5,19.9
LCD_DE  (via drill 0.4)
  Route2 0.25: v73.15,27.62 73.15,28.25 72.83,28.57 72.83,30.1 71.05,31.87 71.05,33.35 70.43,33.97 70.43,38.08 67.5,41.01 67.5,55.1 68.1,55.7 68.1,56.38 v68.25,56.52
  Bottom 0.25: LCD.34 74.5,27.3 74.17,27.62 v73.15,27.62 | v68.25,56.52 67.7,57.08 67.7,61.4 67.3,61.8 67.3,62.8 67.8,63.3 U2.142
LCDCP  (via drill 0.4)
  Route2 0.25: v83.28,31.88 83.05,32.1 82.6,32.1 81.3,33.4 81.3,38.5 78.7,41.1 78.7,47.5 80.58,49.38 v80.58,61.83
  Bottom 0.25: LCD.30 76.5,27.5 77.3,28.3 80.55,28.3 83.28,31.02 v83.28,31.88 | v80.58,61.83 79.4,63 78.1,63 75.1,66 72.9,66 71.8,64.9 U2.150
MCICLK  (via drill 0.4)
  Top 0.254: v94.22,45.42 93.38,45.42 93.08,45.73 84.38,45.73 83.92,46.17 80.58,46.17 v80.55,46.15
  Route2 0.25: v95.4,11.89 94.2,13.09 94.2,21.6
  Route2 0.254: 94.2,21.6 94.2,23.9 94,24.1 94,45.2 v94.22,45.42
  Bottom 0.254: v80.55,46.15 80.25,46.15 78.6,47.8 U2.185
  Bottom 0.508: v95.4,11.89 95.58,11.89 96.13,12.44 MICRO_SD.5
MCICMD  (via drill 0.4)
  Route2 0.25: v95,13.61 95,21.03 95,23.9 94.5,24.4 94.5,40.5 94.85,40.85 v94.85,42.85
  Bottom 0.25: v94.85,42.85 92.2,45.5 87.5,45.5 85.95,47.05 85.95,48.65 85.6,49 82,49 79.2,51.8 U2.177
  Bottom 0.508: v95,13.61 94.34,13.61 93.93,14.02 MICRO_SD.3 93.98,15.43 93.98,17.34 R10.2
MCIDAT0  (via drill 0.4)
